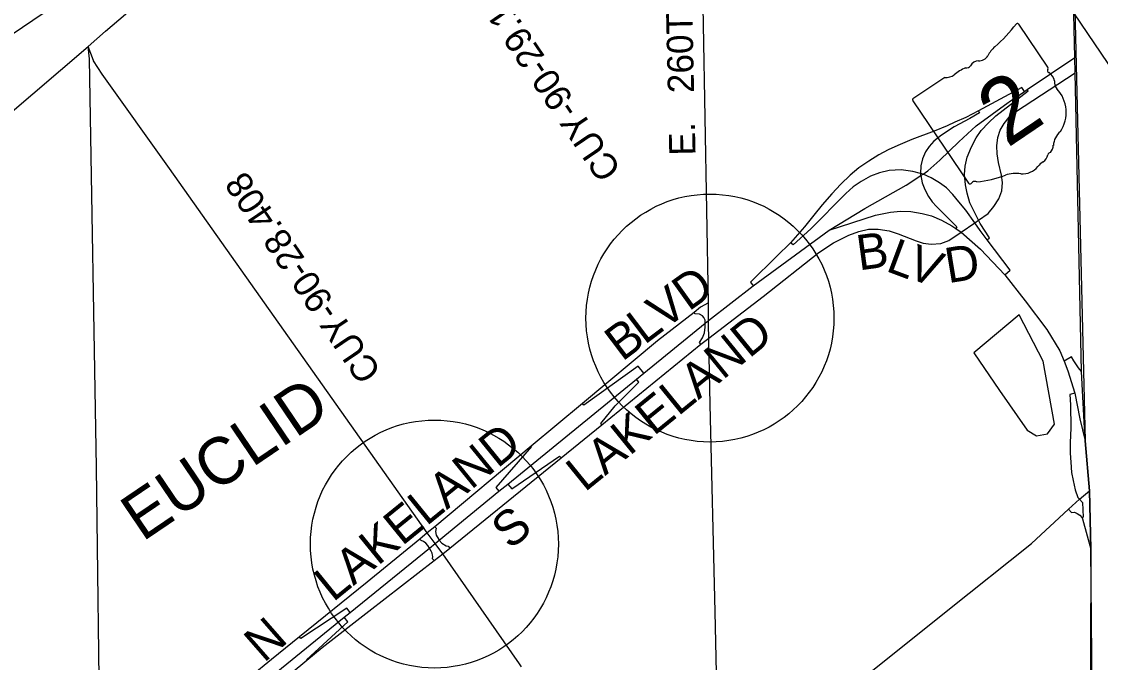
# Model space of a CAD drawing. Extents: x 2139079 to 2262683, y 1235796 to 1334992.
# Drawn here: x 2234072 to 2245568, y 1309915 to 1316743 of the extents above; entities that cross this region are included whole.
import ezdxf

# ---------------------------------------------------------------- set-up
doc = ezdxf.new("R2010")
doc.units = 0
for name, color, linetype in [('Default', 7, 'Continuous'), ('GM_X_Adjacent_County', 7, 'Continuous'), ('GM_X_City_Street', 7, 'Continuous'), ('GM_X_City_Street_Text', 7, 'Continuous'), ('GM_X_Interchange_Ramps', 7, 'Continuous'), ('GM_X_Interstate_Location', 7, 'Continuous'), ('GM_X_Interstate_Route', 7, 'Continuous'), ('GM_X_Minor_Lake', 7, 'Continuous'), ('GM_X_State_Location', 7, 'Continuous'), ('GM_X_State_Route', 7, 'Continuous'), ('GM_X_State_Shield', 7, 'Continuous'), ('GM_X_US_Route', 7, 'Continuous'), ('SH_Text', 7, 'Continuous')]:
    doc.layers.add(name, color=color, linetype=linetype)

msp = doc.modelspace()

# ---------------------------------------------------------------- linework, layer by layer
at = {"layer": 'GM_X_Adjacent_County'}
msp.add_lwpolyline([(2245541, 1302192), (2245528, 1304087), (2245507, 1306573), (2245466, 1311124), (2245451, 1311744), (2245406, 1312275), (2245366, 1313013), (2245298, 1316197), (2245294, 1316360), (2245278, 1317130), (2245271, 1317437), (2245264, 1317789), (2245234, 1319644), (2245190, 1321250), (2245174, 1321990), (2245155, 1322872), (2245144, 1323376), (2245140, 1323785), (2245134, 1324581), (2245318, 1324775), (2245503, 1324980), (2245556, 1325020), (2245646, 1325055)], dxfattribs=at)
at = {"layer": 'GM_X_City_Street'}
for points in [[(2234909, 1308893), (2234870, 1311991), (2234797, 1316346), (2234781, 1316477)], [(2234838, 1316330), (2234781, 1316477)], [(2238395, 1311294), (2235647, 1315176), (2234931, 1316181), (2234839, 1316326), (2234838, 1316330)], [(2236776, 1309663), (2237111, 1309938), (2237274, 1310073), (2237772, 1310459), (2238467, 1311000), (2238560, 1311072), (2238634, 1311133), (2239820, 1312094), (2240255, 1312447), (2241311, 1313304), (2241395, 1313371), (2241975, 1313814), (2242567, 1314282), (2242723, 1314385), (2242887, 1314467), (2242992, 1314505), (2243098, 1314530), (2243198, 1314531), (2243315, 1314514), (2243411, 1314481), (2243606, 1314408), (2243679, 1314382), (2243763, 1314370), (2243868, 1314377), (2243951, 1314412), (2244085, 1314498), (2244229, 1314599), (2244269, 1314627), (2244370, 1314698), (2244433, 1314771), (2244484, 1314855), (2244516, 1314938), (2244524, 1315029), (2244514, 1315108), (2244481, 1315242), (2244466, 1315335), (2244463, 1315418), (2244473, 1315509), (2244500, 1315585), (2244542, 1315658), (2244597, 1315723), (2244661, 1315782), (2245298, 1316197)], [(2241391, 1313747), (2241308, 1313700), (2241239, 1313644), (2240849, 1313342), (2240048, 1312674), (2239503, 1312219), (2238476, 1311361), (2238395, 1311294), (2238315, 1311229), (2237753, 1310771), (2237032, 1310186), (2236735, 1309945), (2236518, 1309769), (2235520, 1308963), (2235213, 1308739), (2235026, 1308631), (2234914, 1308565), (2234865, 1308535)], [(2239398, 1309868), (2239376, 1309899), (2238560, 1311072), (2238478, 1311183), (2238395, 1311294)]]:
    msp.add_lwpolyline(points, dxfattribs=at)
at = {"layer": 'GM_X_Interchange_Ramps'}
for points in [[(2244758, 1315998), (2244729, 1316042), (2244269, 1315791), (2244132, 1315722), (2244018, 1315671), (2243936, 1315633), (2243796, 1315575), (2243557, 1315485), (2243409, 1315424), (2243305, 1315375), (2243207, 1315322), (2243100, 1315254), (2242994, 1315183), (2242900, 1315107), (2242803, 1315012), (2242704, 1314908), (2242603, 1314791), (2242514, 1314681), (2242416, 1314556), (2242265, 1314387), (2242118, 1314242), (2241838, 1313968), (2241868, 1313928)], [(2244362, 1314419), (2244386, 1314437), (2244286, 1314591), (2244269, 1314627), (2244226, 1314713), (2244176, 1314812), (2244147, 1314914), (2244129, 1315005), (2244120, 1315115), (2244126, 1315203), (2244146, 1315300), (2244193, 1315410), (2244243, 1315503), (2244298, 1315582), (2244375, 1315664), (2244452, 1315738), (2244798, 1316004), (2244788, 1316018)], [(2244269, 1315791), (2244280, 1315771), (2244176, 1315712), (2244008, 1315623), (2243875, 1315533), (2243794, 1315470), (2243743, 1315412), (2243703, 1315356), (2243672, 1315281), (2243655, 1315205), (2243652, 1315124), (2243652, 1315112), (2243654, 1315102), (2243669, 1315026), (2243697, 1314952), (2243737, 1314878), (2243776, 1314822), (2243820, 1314774), (2244039, 1314557), (2244027, 1314538)], [(2244548, 1314046), (2244607, 1314095), (2244362, 1314419), (2244287, 1314518), (2244229, 1314599), (2244135, 1314732), (2244059, 1314823), (2243996, 1314902), (2243927, 1314970), (2243852, 1315026), (2243764, 1315078), (2243678, 1315118), (2243652, 1315124), (2243570, 1315145), (2243446, 1315164), (2243318, 1315157), (2243212, 1315133), (2243116, 1315096), (2243018, 1315039), (2242932, 1314981), (2242856, 1314912), (2242483, 1314533), (2242293, 1314363), (2242265, 1314387)], [(2241311, 1313304), (2241297, 1313322), (2241329, 1313374), (2241349, 1313426), (2241357, 1313488), (2241356, 1313531), (2241355, 1313561), (2241343, 1313589), (2241326, 1313608), (2241296, 1313624), (2241251, 1313629), (2241239, 1313644)], [(2245366, 1313013), (2245333, 1313053), (2245285, 1313129), (2245260, 1313171), (2245180, 1313123)], [(2240702, 1312997), (2240641, 1313071), (2240062, 1312657), (2240048, 1312674)], [(2240255, 1312447), (2240245, 1312459), (2240397, 1312649), (2240649, 1312900), (2240623, 1312932)], [(2245296, 1312782), (2245240, 1312771), (2245249, 1312658), (2245253, 1312415), (2245247, 1312253), (2245245, 1312145), (2245251, 1312047), (2245261, 1311939), (2245278, 1311852), (2245298, 1311755), (2245327, 1311673), (2245343, 1311654)], [(2239503, 1312219), (2239506, 1312215), (2239124, 1311779), (2239158, 1311738)], [(2239253, 1311815), (2239295, 1311765), (2239804, 1312114), (2239820, 1312094)], [(2245343, 1311654), (2245375, 1311617), (2245384, 1311462), (2245372, 1311456)], [(2245228, 1311548), (2245261, 1311511), (2245293, 1311514), (2245320, 1311503), (2245347, 1311485), (2245372, 1311456), (2245377, 1311444), (2245466, 1311123)], [(2238476, 1311361), (2238488, 1311345), (2238481, 1311311), (2238491, 1311271), (2238517, 1311225), (2238522, 1311219), (2238550, 1311186), (2238595, 1311158), (2238617, 1311155), (2238634, 1311133)], [(2238467, 1311000), (2238452, 1311019), (2238454, 1311044), (2238451, 1311056), (2238446, 1311078), (2238436, 1311099), (2238417, 1311133), (2238401, 1311160), (2238380, 1311185), (2238353, 1311204), (2238329, 1311212), (2238315, 1311229)], [(2237574, 1310448), (2237537, 1310494), (2237046, 1310168), (2237032, 1310186)], [(2237111, 1309938), (2237107, 1309942), (2237549, 1310347), (2237510, 1310396)]]:
    msp.add_lwpolyline(points, dxfattribs=at)
at = {"layer": 'GM_X_Interstate_Route'}
for points in [[(2245142, 1323484), (2245178, 1321773), (2245406, 1312275), (2245451, 1311744), (2245466, 1311124), (2245458, 1308807), (2245473, 1308109), (2243489, 1308053), (2243515, 1306895), (2242283, 1306903), (2241498, 1306888), (2241571, 1303589)], [(2245142, 1323484), (2245178, 1321773), (2245406, 1312275), (2245451, 1311744), (2245466, 1311124), (2245458, 1308807), (2245473, 1308109), (2243489, 1308053), (2243515, 1306895), (2242283, 1306903), (2241498, 1306888), (2241571, 1303589)], [(2242679, 1314520), (2242679, 1314520), (2243170, 1314681), (2243332, 1314714), (2243436, 1314723), (2243548, 1314718), (2243667, 1314699), (2243766, 1314673), (2243873, 1314627), (2243983, 1314567), (2243985, 1314566)], [(2243985, 1314566), (2244027, 1314538), (2244085, 1314498), (2244289, 1314319), (2244548, 1314046), (2244765, 1313768), (2244998, 1313461), (2245134, 1313234), (2245180, 1313123), (2245222, 1313022), (2245296, 1312782), (2245350, 1312509), (2245406, 1312275)], [(2241390, 1313558), (2241868, 1313928), (2242679, 1314520)], [(2232924, 1307142), (2234220, 1307872), (2234786, 1308269), (2234817, 1308291), (2234860, 1308321), (2234917, 1308361), (2234987, 1308413), (2235511, 1308800), (2235909, 1309114), (2236104, 1309268), (2236747, 1309775), (2237510, 1310396), (2237574, 1310448), (2238417, 1311133), (2238478, 1311183), (2238522, 1311219), (2239158, 1311738), (2239253, 1311815), (2240623, 1312932), (2240702, 1312997), (2241356, 1313531), (2241390, 1313558)]]:
    msp.add_lwpolyline(points, dxfattribs=at)
at = {"layer": 'GM_X_Minor_Lake'}
for points in [[(2244702, 1313620), (2244218, 1313214), (2244494, 1312813)], [(2244494, 1312813), (2244786, 1312389), (2244885, 1312328), (2245005, 1312352), (2245078, 1312453), (2244958, 1313125), (2244702, 1313620)]]:
    msp.add_lwpolyline(points, dxfattribs=at)
at = {"layer": 'GM_X_State_Route'}
for points in [[(2241391, 1313507), (2241390, 1313558), (2241391, 1313747), (2241301, 1318685), (2241260, 1320563)], [(2233896, 1315721), (2234781, 1316477), (2234965, 1316640), (2235180, 1316822), (2235401, 1317014), (2235612, 1317192), (2235811, 1317362), (2235970, 1317500), (2236130, 1317631), (2236291, 1317777), (2236370, 1317843)], [(2244585, 1315881), (2244595, 1315888), (2244758, 1315998), (2244788, 1316018), (2245294, 1316360)], [(2242679, 1314520), (2243058, 1314752), (2243496, 1315000), (2243654, 1315102), (2243678, 1315118), (2243729, 1315151), (2243856, 1315265), (2244059, 1315460), (2244243, 1315631), (2244585, 1315881)], [(2241395, 1313349), (2241395, 1313371), (2241391, 1313507)], [(2241411, 1312664), (2241395, 1313349)], [(2241462, 1310453), (2241411, 1312664)], [(2241744, 1308690), (2241641, 1308805), (2241562, 1308908), (2241532, 1308957), (2241513, 1309011), (2241499, 1309083), (2241491, 1309152), (2241462, 1310453)]]:
    msp.add_lwpolyline(points, dxfattribs=at)
at = {"layer": 'GM_X_State_Shield'}
for p, q in [((2245007, 1316256), (2244697, 1316714)), ((2245007, 1316256), (2245007, 1316256)), ((2243908, 1316148), (2243570, 1315919)), ((2243569, 1315897), (2244162, 1315022))]:
    msp.add_line(p, q, dxfattribs=at)
for centre, radius, start, end in [((2243493, 1317607), 1476, 309.9559, 323.0178), ((2244683, 1316707), 15.5, 25.9735, 131.8494), ((2244272, 1316437), 113, 267.9676, 328.9396), ((2244638, 1316253), 297, 131.4576, 154.8802), ((2244143, 1316294), 45.1, 253.9035, 331.2138), ((2244266, 1316230), 93.8, 88.5781, 153.2525), ((2244994, 1316245), 16.6, 323.7152, 41.8455), ((2243920, 1316304), 156, 265.7309, 305.2233), ((2244364, 1315740), 562, 114.5981, 129.0997), ((2245027, 1316221), 24, 142.0554, 244.4484), ((2244940, 1316077), 144, 14.1444, 57.761), ((2245183, 1316096), 105, 170.9179, 221.041), ((2244834, 1315775), 369, 326.4203, 43.0972), ((2243581, 1315907), 16.1, 132.2415, 222.2415), ((2245268, 1315412), 202, 128.5145, 176.6881), ((2245039, 1315317), 31.8, 99.8631, 166.7598), ((2244947, 1315430), 119, 316.9846, 357.3885), ((2245045, 1315099), 174, 119.8065, 145.3213), ((2244897, 1315344), 113, 302.8884, 349.6607), ((2244168, 1316099), 1066, 274.5243, 291.3099), ((2244669, 1314792), 334, 81.2955, 109.9474), ((2244739, 1315333), 212, 264.8118, 320.4032), ((2244176, 1315029), 16.3, 206.0698, 292.418), ((2244118, 1315120), 124, 301.4504, 314.7152), ((2244232, 1314996), 44.8, 63.8598, 127.3831)]:
    msp.add_arc(centre, radius, start, end, dxfattribs=at)
at = {"layer": 'GM_X_US_Route'}
msp.add_lwpolyline([(2202868, 1295541), (2210354, 1284489), (2249318, 1310882), (2241832, 1321934)], close=True, dxfattribs=at)
msp.add_lwpolyline([(2241744, 1308690), (2241900, 1308822), (2242089, 1308990), (2242250, 1309114), (2242960, 1309687), (2243940, 1310472), (2244832, 1311181), (2245228, 1311548), (2245343, 1311654), (2245451, 1311744)], dxfattribs=at)
at = {"layer": 'SH_Text'}
for centre in [(2241407, 1313584), (2238471, 1311176)]:
    msp.add_circle(centre, 1321, dxfattribs=at)

# ---------------------------------------------------------------- texts
at = {"layer": 'Default'}
for s, p in [('CUY-90-29.113', (2240471, 1315165)), ('CUY-90-28.408', (2237914, 1313013))]:
    msp.add_text(s, height=280, rotation=124.1113, dxfattribs=at).set_placement(p)
at = {"layer": 'GM_X_City_Street_Text'}
for s, rotation, p in [('B', 7.6771, (2242995, 1314091)), ('L', 339.4567, (2243268, 1314090)), ('V', 339.4834, (2243485, 1314025)), ('D', 9.4094, (2243945, 1313954)), ('D', 35.5148, (2241180, 1313649)), ('V', 37.0928, (2240919, 1313452)), ('L', 37.0939, (2240709, 1313293)), ('LAKELAND', 39.1315, (2240073, 1311723)), ('B', 37.0933, (2240472, 1313114)), ('LAKELAND', 39.1315, (2237391, 1310551)), ('S', 39.8092, (2239279, 1311107)), ('N', 41.1879, (2236654, 1309903))]:
    msp.add_text(s, height=375, rotation=rotation, dxfattribs=at).set_placement(p)
at = {"layer": 'GM_X_Interchange_Ramps'}
msp.add_text('E.   260TH   ST.', height=280, rotation=91.3108, dxfattribs=at).set_placement((2241254, 1315318))
at = {"layer": 'GM_X_Interstate_Location'}
for s in ['-', '.', ',']:
    msp.add_text(s, height=1, dxfattribs=at).set_placement((2238408, 1311132))
msp.add_text('90', height=1, rotation=0, dxfattribs=at).set_placement((2238204, 1310925))
at = {"layer": 'GM_X_State_Location'}
for s in ['s', 'r']:
    msp.add_text(s, height=1, dxfattribs=at).set_placement((2244008, 1315288))
msp.add_text('2', height=1, rotation=0, dxfattribs=at).set_placement((2243858, 1315215))
at = {"layer": 'GM_X_State_Route'}
msp.add_text('EUCLID', height=500, rotation=34.1113, dxfattribs=at).set_placement((2235360, 1311195))
at = {"layer": 'GM_X_State_Shield'}
msp.add_text('2', height=696, rotation=34.1114, dxfattribs=at).set_placement((2244574, 1315391))

doc.saveas('drawing.dxf')
